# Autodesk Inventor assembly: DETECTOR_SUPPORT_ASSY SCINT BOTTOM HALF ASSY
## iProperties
Shininess: 64.0
Length Units: 11272
Angle Units: 11279
Time Units: 11290
Mass Units: 11286
Length Display Precision: 3
Angle Display Precision: 2
Compacted: True
Part Number: DETECTOR_SUPPORT_ASSY SCINT BOTTOM HALF ASSY
Document SubType Name: Assembly
Created: 2004-08
Designer: John Blackburn
Manufacturer: Standard
Standards Organization: Custom
Density: 0.0
Volumn: 0.0
Area: 0.0
PropertySet Name: Model Information
Control State: 0
Master: False
Checked Out: False
Author: John Blackburn
